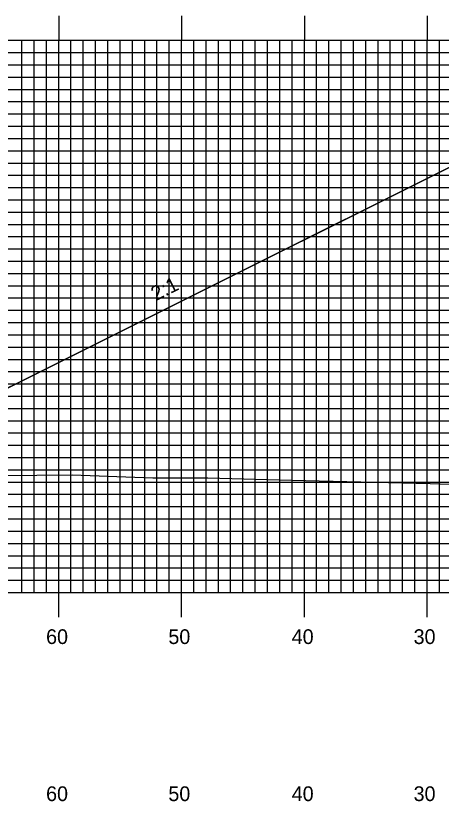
# Model space of a CAD drawing. Extents: x 1785795 to 1786139, y 442591 to 442811.
# Drawn here: x 1785897.6 to 1785932.2, y 442656.6 to 442720.7 of the extents above; entities that cross this region are included whole.
import ezdxf

# ---------------------------------------------------------------- set-up
doc = ezdxf.new("R2010")
doc.units = 0
for name, color, linetype in [('ANNOTATION', 7, 'Continuous'), ('D_Roadway_Centerline', 7, 'Continuous'), ('D_Roadway_SlopeLines', 7, 'Continuous'), ('H_V ANNOTATION', 7, 'Continuous'), ('MAJOR', 7, 'Continuous'), ('MINOR', 7, 'Continuous'), ('S_Roadway_Centerline', 7, 'Continuous')]:
    doc.layers.add(name, color=color, linetype=linetype)

msp = doc.modelspace()

# ---------------------------------------------------------------- linework, layer by layer
at = {"layer": 'D_Roadway_Centerline'}
msp.add_lwpolyline([(1785883.536, 442683.648), (1785933.236, 442708.498), (1785938.052, 442710.906), (1785941.052, 442711.026), (1785949.052, 442711.346), (1785961.052, 442711.61), (1785973.052, 442711.874), (1785981.052, 442711.554), (1785984.052, 442711.434), (1785988.802, 442709.059), (1786042.988, 442681.966)], dxfattribs=at)
at = {"layer": 'D_Roadway_SlopeLines'}
msp.add_lwpolyline([(1785938.052, 442710.906), (1785883.536, 442683.648)], dxfattribs=at)
at = {"layer": 'MAJOR'}
for p, q in [((1785901.052, 442720.669), (1785901.052, 442718.665)), ((1785911.052, 442720.669), (1785911.052, 442718.665)), ((1785921.052, 442720.669), (1785921.052, 442718.665)), ((1785931.052, 442720.669), (1785931.052, 442718.665)), ((1785821.052, 442718.665), (1786101.052, 442718.665)), ((1785821.052, 442718.665), (1786101.052, 442718.665)), ((1785901.052, 442673.665), (1785901.052, 442718.665)), ((1785911.052, 442673.665), (1785911.052, 442718.665)), ((1785921.052, 442673.665), (1785921.052, 442718.665)), ((1785931.052, 442673.665), (1785931.052, 442718.665)), ((1785821.052, 442713.665), (1786101.052, 442713.665)), ((1785821.052, 442708.665), (1786101.052, 442708.665)), ((1785821.052, 442703.665), (1786101.052, 442703.665)), ((1785821.052, 442698.665), (1786101.052, 442698.665)), ((1785821.052, 442693.665), (1786101.052, 442693.665)), ((1785821.052, 442688.665), (1786101.052, 442688.665)), ((1785821.052, 442683.665), (1786101.052, 442683.665)), ((1785821.052, 442678.665), (1786101.052, 442678.665)), ((1785821.052, 442673.665), (1786101.052, 442673.665)), ((1785821.052, 442673.665), (1786101.052, 442673.665)), ((1785901.052, 442671.661), (1785901.052, 442673.665)), ((1785911.052, 442671.661), (1785911.052, 442673.665)), ((1785921.052, 442671.661), (1785921.052, 442673.665)), ((1785931.052, 442671.661), (1785931.052, 442673.665))]:
    msp.add_line(p, q, dxfattribs=at)
at = {"layer": 'MINOR'}
for p, q in [((1785898.052, 442673.665), (1785898.052, 442718.665)), ((1785899.052, 442673.665), (1785899.052, 442718.665)), ((1785900.052, 442673.665), (1785900.052, 442718.665)), ((1785902.052, 442673.665), (1785902.052, 442718.665)), ((1785903.052, 442673.665), (1785903.052, 442718.665)), ((1785904.052, 442673.665), (1785904.052, 442718.665)), ((1785905.052, 442673.665), (1785905.052, 442718.665)), ((1785906.052, 442673.665), (1785906.052, 442718.665)), ((1785907.052, 442673.665), (1785907.052, 442718.665)), ((1785908.052, 442673.665), (1785908.052, 442718.665)), ((1785909.052, 442673.665), (1785909.052, 442718.665)), ((1785910.052, 442673.665), (1785910.052, 442718.665)), ((1785912.052, 442673.665), (1785912.052, 442718.665)), ((1785913.052, 442673.665), (1785913.052, 442718.665)), ((1785914.052, 442673.665), (1785914.052, 442718.665)), ((1785915.052, 442673.665), (1785915.052, 442718.665)), ((1785916.052, 442673.665), (1785916.052, 442718.665)), ((1785917.052, 442673.665), (1785917.052, 442718.665)), ((1785918.052, 442673.665), (1785918.052, 442718.665)), ((1785919.052, 442673.665), (1785919.052, 442718.665)), ((1785920.052, 442673.665), (1785920.052, 442718.665)), ((1785922.052, 442673.665), (1785922.052, 442718.665)), ((1785923.052, 442673.665), (1785923.052, 442718.665)), ((1785924.052, 442673.665), (1785924.052, 442718.665)), ((1785925.052, 442673.665), (1785925.052, 442718.665)), ((1785926.052, 442673.665), (1785926.052, 442718.665)), ((1785927.052, 442673.665), (1785927.052, 442718.665)), ((1785928.052, 442673.665), (1785928.052, 442718.665)), ((1785929.052, 442673.665), (1785929.052, 442718.665)), ((1785930.052, 442673.665), (1785930.052, 442718.665)), ((1785932.052, 442673.665), (1785932.052, 442718.665)), ((1785821.052, 442717.665), (1786101.052, 442717.665)), ((1785821.052, 442716.665), (1786101.052, 442716.665)), ((1785821.052, 442715.665), (1786101.052, 442715.665)), ((1785821.052, 442714.665), (1786101.052, 442714.665)), ((1785821.052, 442712.665), (1786101.052, 442712.665)), ((1785821.052, 442711.665), (1786101.052, 442711.665)), ((1785821.052, 442710.665), (1786101.052, 442710.665)), ((1785821.052, 442709.665), (1786101.052, 442709.665)), ((1785821.052, 442707.665), (1786101.052, 442707.665)), ((1785821.052, 442706.665), (1786101.052, 442706.665)), ((1785821.052, 442705.665), (1786101.052, 442705.665)), ((1785821.052, 442704.665), (1786101.052, 442704.665)), ((1785821.052, 442702.665), (1786101.052, 442702.665)), ((1785821.052, 442701.665), (1786101.052, 442701.665)), ((1785821.052, 442700.665), (1786101.052, 442700.665)), ((1785821.052, 442699.665), (1786101.052, 442699.665)), ((1785821.052, 442697.665), (1786101.052, 442697.665)), ((1785821.052, 442696.665), (1786101.052, 442696.665)), ((1785821.052, 442695.665), (1786101.052, 442695.665)), ((1785821.052, 442694.665), (1786101.052, 442694.665)), ((1785821.052, 442692.665), (1786101.052, 442692.665)), ((1785821.052, 442691.665), (1786101.052, 442691.665)), ((1785821.052, 442690.665), (1786101.052, 442690.665)), ((1785821.052, 442689.665), (1786101.052, 442689.665)), ((1785821.052, 442687.665), (1786101.052, 442687.665)), ((1785821.052, 442686.665), (1786101.052, 442686.665)), ((1785821.052, 442685.665), (1786101.052, 442685.665)), ((1785821.052, 442684.665), (1786101.052, 442684.665)), ((1785821.052, 442682.665), (1786101.052, 442682.665)), ((1785821.052, 442681.665), (1786101.052, 442681.665)), ((1785821.052, 442680.665), (1786101.052, 442680.665)), ((1785821.052, 442679.665), (1786101.052, 442679.665)), ((1785821.052, 442677.665), (1786101.052, 442677.665)), ((1785821.052, 442676.665), (1786101.052, 442676.665)), ((1785821.052, 442675.665), (1786101.052, 442675.665)), ((1785821.052, 442674.665), (1786101.052, 442674.665))]:
    msp.add_line(p, q, dxfattribs=at)
at = {"layer": 'S_Roadway_Centerline'}
msp.add_lwpolyline([(1785821.052, 442685.62), (1785825.196, 442685.245), (1785831.921, 442684.996), (1785841.547, 442685.106), (1785844.548, 442685.226), (1785846.721, 442685.034), (1785866.573, 442683.981), (1785867.347, 442683.985), (1785867.961, 442683.946), (1785879.157, 442683.974), (1785888.487, 442683.28), (1785893.47, 442683.161), (1785902.137, 442683.241), (1785908.71, 442683.02), (1785913.181, 442683.003), (1785919.996, 442682.829), (1785931.287, 442682.542), (1785945.812, 442682.061)], dxfattribs=at)

# ---------------------------------------------------------------- texts
at = {"layer": 'ANNOTATION'}
msp.add_text('2:1', height=1.2, rotation=26.56505, dxfattribs=at).set_placement((1785908.939, 442697.386))
at = {"layer": 'H_V ANNOTATION'}
for s, p in [('60', (1785900.024, 442669.465)), ('50', (1785909.981, 442669.465)), ('40', (1785920.024, 442669.465)), ('30', (1785929.949, 442669.465)), ('60', (1785900.024, 442656.665)), ('50', (1785909.981, 442656.665)), ('40', (1785920.024, 442656.665)), ('30', (1785929.949, 442656.665))]:
    msp.add_text(s, height=1.2, dxfattribs=at).set_placement(p)

doc.saveas('drawing.dxf')
